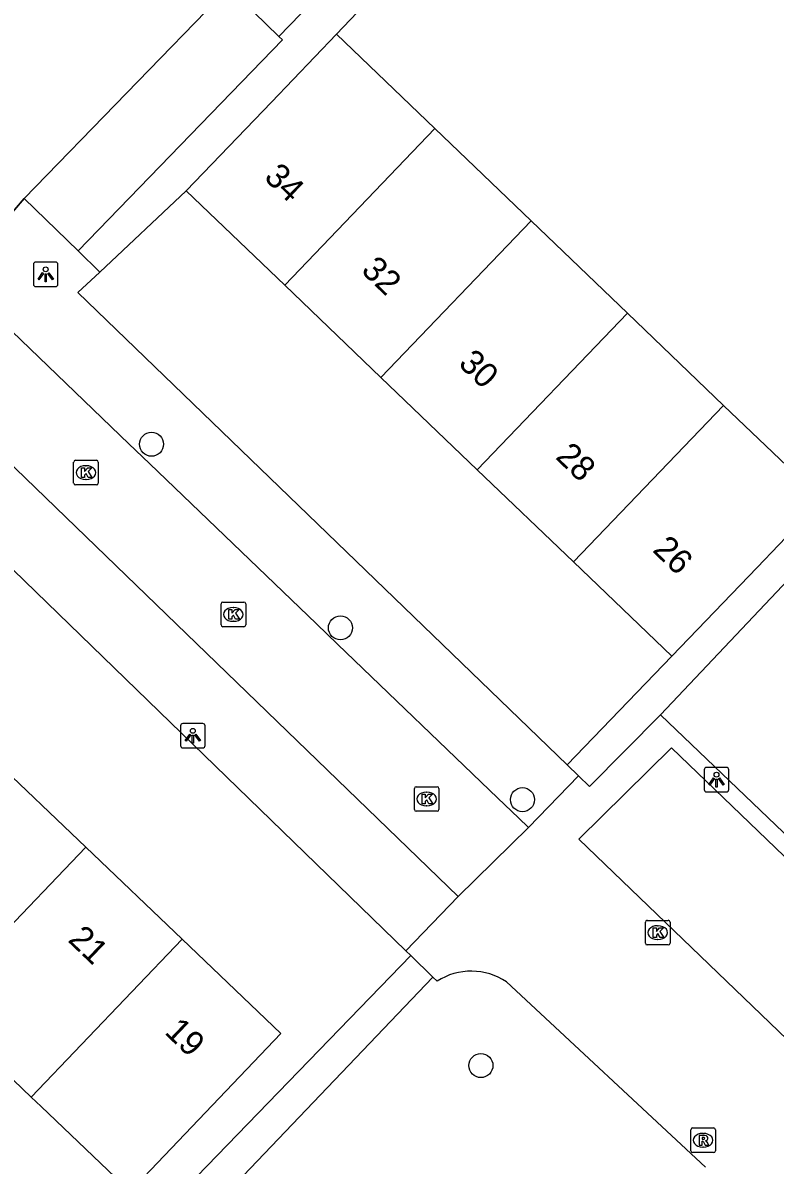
# Model space of a CAD drawing. Extents: x 158474 to 159560, y 388525 to 389605.
# Drawn here: x 159067.09 to 159097.68, y 388787.5 to 388833.95 of the extents above; entities that cross this region are included whole.
import ezdxf

# ---------------------------------------------------------------- set-up
doc = ezdxf.new("R2010")
doc.units = 0
for name, color, linetype in [('IMGEO_Boom', 7, 'Continuous'), ('IMGEO_Kolk', 7, 'Continuous'), ('IMGEO_Lichtpunt', 7, 'Continuous'), ('IMGEO_Muur', 7, 'Continuous'), ('IMGEO_Pand', 7, 'Continuous'), ('IMGEO_Pand_nummerreeks', 7, 'Continuous'), ('IMGEO_Rijbaan_lokaal_open', 7, 'Continuous'), ('IMGEO_Rioolput', 7, 'Continuous'), ('IMGEO_Voetpad_open', 7, 'Continuous')]:
    doc.layers.add(name, color=color, linetype=linetype)

msp = doc.modelspace()

# ---------------------------------------------------------------- linework, layer by layer
at = {"layer": 'IMGEO_Boom'}
for centre in [(159072.325, 388816.819), (159080.007, 388809.351), (159087.409, 388802.366), (159085.718, 388791.554)]:
    msp.add_circle(centre, 0.489, dxfattribs=at)
at = {"layer": 'IMGEO_Kolk'}
for p, q in [((159069.159, 388815.239), (159069.159, 388816.091)), ((159069.234, 388816.165), (159070.086, 388816.165)), ((159069.647, 388815.945), (159069.672, 388815.945)), ((159070.16, 388816.091), (159070.16, 388815.239)), ((159070.086, 388815.165), (159069.234, 388815.165)), ((159069.67, 388815.385), (159069.645, 388815.385)), ((159075.228, 388810.399), (159076.08, 388810.399)), ((159075.153, 388809.473), (159075.153, 388810.325)), ((159075.641, 388810.179), (159075.666, 388810.179)), ((159076.154, 388810.325), (159076.154, 388809.473)), ((159075.664, 388809.619), (159075.639, 388809.619)), ((159076.08, 388809.399), (159075.228, 388809.399)), ((159083.012, 388801.967), (159083.012, 388802.819)), ((159083.087, 388802.893), (159083.939, 388802.893)), ((159083.5, 388802.673), (159083.525, 388802.673)), ((159084.013, 388802.819), (159084.013, 388801.967)), ((159083.523, 388802.113), (159083.498, 388802.113)), ((159083.939, 388801.893), (159083.087, 388801.893)), ((159092.408, 388796.533), (159092.408, 388797.385)), ((159092.483, 388797.459), (159093.335, 388797.459)), ((159093.409, 388797.385), (159093.409, 388796.533)), ((159092.896, 388797.239), (159092.921, 388797.239)), ((159093.335, 388796.459), (159092.483, 388796.459)), ((159092.919, 388796.679), (159092.894, 388796.679))]:
    msp.add_line(p, q, dxfattribs=at)
for points in [[(159069.159, 388815.239), (159069.159, 388816.091)], [(159069.234, 388816.165), (159070.086, 388816.165)], [(159070.16, 388816.091), (159070.16, 388815.239)], [(159069.48, 388815.865), (159069.603, 388815.865), (159069.603, 388815.714), (159069.733, 388815.865), (159069.897, 388815.865), (159069.751, 388815.714), (159069.904, 388815.465), (159069.752, 388815.465), (159069.667, 388815.629), (159069.603, 388815.562), (159069.603, 388815.465), (159069.48, 388815.465), (159069.48, 388815.865)], [(159070.086, 388815.165), (159069.234, 388815.165)], [(159075.228, 388810.399), (159076.08, 388810.399)], [(159075.153, 388809.473), (159075.153, 388810.325)], [(159075.474, 388810.099), (159075.597, 388810.099), (159075.597, 388809.948), (159075.727, 388810.099), (159075.891, 388810.099), (159075.745, 388809.948), (159075.898, 388809.699), (159075.746, 388809.699), (159075.661, 388809.863), (159075.597, 388809.796), (159075.597, 388809.699), (159075.474, 388809.699), (159075.474, 388810.099)], [(159076.154, 388810.325), (159076.154, 388809.473)], [(159076.08, 388809.399), (159075.228, 388809.399)], [(159083.012, 388801.967), (159083.012, 388802.819)], [(159083.087, 388802.893), (159083.939, 388802.893)], [(159083.333, 388802.593), (159083.456, 388802.593), (159083.456, 388802.442), (159083.586, 388802.593), (159083.75, 388802.593), (159083.604, 388802.442), (159083.757, 388802.193), (159083.605, 388802.193), (159083.52, 388802.357), (159083.456, 388802.29), (159083.456, 388802.193), (159083.333, 388802.193), (159083.333, 388802.593)], [(159084.013, 388802.819), (159084.013, 388801.967)], [(159083.939, 388801.893), (159083.087, 388801.893)], [(159092.408, 388796.533), (159092.408, 388797.385)], [(159092.483, 388797.459), (159093.335, 388797.459)], [(159093.409, 388797.385), (159093.409, 388796.533)], [(159092.729, 388797.159), (159092.852, 388797.159), (159092.852, 388797.008), (159092.982, 388797.159), (159093.146, 388797.159), (159093, 388797.008), (159093.153, 388796.759), (159093.001, 388796.759), (159092.916, 388796.923), (159092.852, 388796.856), (159092.852, 388796.759), (159092.729, 388796.759), (159092.729, 388797.159)], [(159093.335, 388796.459), (159092.483, 388796.459)]]:
    msp.add_lwpolyline(points, dxfattribs=at)
for centre, start, end in [((159069.236, 388816.089), 91.552, 178.448), ((159069.236, 388816.089), 91.552, 178.448), ((159070.084, 388816.089), 1.552, 88.448), ((159070.084, 388816.089), 1.552, 88.448), ((159069.236, 388815.241), 181.552, 268.448), ((159069.236, 388815.241), 181.552, 268.448), ((159070.084, 388815.241), 271.552, 358.448), ((159070.084, 388815.241), 271.552, 358.448), ((159075.23, 388810.323), 91.552, 178.448), ((159075.23, 388810.323), 91.552, 178.448), ((159076.078, 388810.323), 1.552, 88.448), ((159076.078, 388810.323), 1.552, 88.448), ((159075.23, 388809.475), 181.552, 268.448), ((159075.23, 388809.475), 181.552, 268.448), ((159076.078, 388809.475), 271.552, 358.448), ((159076.078, 388809.475), 271.552, 358.448), ((159083.089, 388802.817), 91.552, 178.448), ((159083.089, 388802.817), 91.552, 178.448), ((159083.937, 388802.817), 1.552, 88.448), ((159083.937, 388802.817), 1.552, 88.448), ((159083.089, 388801.969), 181.552, 268.448), ((159083.089, 388801.969), 181.552, 268.448), ((159083.937, 388801.969), 271.552, 358.448), ((159083.937, 388801.969), 271.552, 358.448), ((159092.485, 388797.383), 91.552, 178.448), ((159092.485, 388797.383), 91.552, 178.448), ((159093.333, 388797.383), 1.552, 88.448), ((159093.333, 388797.383), 1.552, 88.448), ((159092.485, 388796.535), 181.552, 268.448), ((159092.485, 388796.535), 181.552, 268.448), ((159093.333, 388796.535), 271.552, 358.448), ((159093.333, 388796.535), 271.552, 358.448)]:
    msp.add_arc(centre, 0.0765, start, end, dxfattribs=at)
for centre, major_axis, ratio, start_param, end_param in [((159069.646, 388815.665), (-0.387, 0.002), 0.722429, 4.712389, 7.853982), ((159069.671, 388815.665), (-0.39, 0.002), 0.717154, 1.570796, 4.712389), ((159075.64, 388809.899), (-0.387, 0.002), 0.722429, 4.712389, 7.853982), ((159075.665, 388809.899), (-0.39, 0.002), 0.717154, 1.570796, 4.712389), ((159083.499, 388802.393), (-0.387, 0.002), 0.722429, 4.712389, 7.853982), ((159083.524, 388802.393), (-0.39, 0.002), 0.717154, 1.570796, 4.712389), ((159092.895, 388796.959), (-0.387, 0.002), 0.722429, 4.712389, 7.853982), ((159092.92, 388796.959), (-0.39, 0.002), 0.717154, 1.570796, 4.712389)]:
    msp.add_ellipse(centre, major_axis=major_axis, ratio=ratio, start_param=start_param, end_param=end_param, dxfattribs=at)
at = {"layer": 'IMGEO_Lichtpunt'}
for p, q in [((159067.523, 388824.132), (159067.523, 388823.325)), ((159067.523, 388824.132), (159067.523, 388823.325)), ((159068.425, 388824.227), (159067.617, 388824.227)), ((159068.425, 388824.227), (159067.617, 388824.227)), ((159068.519, 388823.325), (159068.519, 388824.132)), ((159068.519, 388823.325), (159068.519, 388824.132)), ((159067.617, 388823.231), (159068.425, 388823.231)), ((159067.617, 388823.231), (159068.425, 388823.231)), ((159073.505, 388805.369), (159073.505, 388804.562)), ((159073.505, 388805.369), (159073.505, 388804.562)), ((159074.407, 388805.464), (159073.599, 388805.464)), ((159074.407, 388805.464), (159073.599, 388805.464)), ((159074.501, 388804.562), (159074.501, 388805.369)), ((159074.501, 388804.562), (159074.501, 388805.369)), ((159073.599, 388804.468), (159074.407, 388804.468)), ((159073.599, 388804.468), (159074.407, 388804.468)), ((159094.797, 388803.585), (159094.797, 388802.778)), ((159094.797, 388803.585), (159094.797, 388802.778)), ((159095.699, 388803.68), (159094.891, 388803.68)), ((159095.699, 388803.68), (159094.891, 388803.68)), ((159095.793, 388802.778), (159095.793, 388803.585)), ((159095.793, 388802.778), (159095.793, 388803.585)), ((159094.891, 388802.684), (159095.699, 388802.684)), ((159094.891, 388802.684), (159095.699, 388802.684))]:
    msp.add_line(p, q, dxfattribs=at)
for points in [[(159067.897, 388823.796), (159067.936, 388823.768), (159067.748, 388823.506), (159067.71, 388823.533), (159067.897, 388823.796)], [(159067.999, 388823.748), (159068.046, 388823.748), (159068.046, 388823.426), (159067.999, 388823.426), (159067.999, 388823.748)], [(159068.109, 388823.768), (159068.147, 388823.795), (159068.334, 388823.533), (159068.295, 388823.505), (159068.109, 388823.768)], [(159073.879, 388805.033), (159073.918, 388805.005), (159073.73, 388804.743), (159073.692, 388804.77), (159073.879, 388805.033)], [(159073.981, 388804.985), (159074.028, 388804.985), (159074.028, 388804.663), (159073.981, 388804.663), (159073.981, 388804.985)], [(159074.091, 388805.005), (159074.129, 388805.032), (159074.316, 388804.77), (159074.277, 388804.742), (159074.091, 388805.005)], [(159095.171, 388803.249), (159095.21, 388803.221), (159095.022, 388802.959), (159094.984, 388802.986), (159095.171, 388803.249)], [(159095.273, 388803.201), (159095.32, 388803.201), (159095.32, 388802.879), (159095.273, 388802.879), (159095.273, 388803.201)], [(159095.383, 388803.221), (159095.421, 388803.248), (159095.608, 388802.986), (159095.569, 388802.958), (159095.383, 388803.221)]]:
    msp.add_lwpolyline(points, dxfattribs=at)
for centre in [(159068.022, 388823.93), (159074.004, 388805.167), (159095.296, 388803.383)]:
    msp.add_circle(centre, 0.0994, dxfattribs=at)
for centre, start, end in [((159067.617, 388824.132), 90, 180), ((159067.617, 388824.132), 90, 180), ((159068.425, 388824.132), 0, 90), ((159068.425, 388824.132), 0, 90), ((159067.617, 388823.325), 180, 270), ((159067.617, 388823.325), 180, 270), ((159068.425, 388823.325), 270, 0), ((159068.425, 388823.325), 270, 360), ((159073.599, 388805.369), 90, 180), ((159073.599, 388805.369), 90, 180), ((159074.407, 388805.369), 0, 90), ((159074.407, 388805.369), 0, 90), ((159073.599, 388804.562), 180, 270), ((159073.599, 388804.562), 180, 270), ((159074.407, 388804.562), 270, 0), ((159074.407, 388804.562), 270, 360), ((159094.891, 388803.585), 90, 180), ((159094.891, 388803.585), 90, 180), ((159095.699, 388803.585), 0, 90), ((159095.699, 388803.585), 0, 90), ((159094.891, 388802.778), 180, 270), ((159094.891, 388802.778), 180, 270), ((159095.699, 388802.778), 270, 0), ((159095.699, 388802.778), 270, 360)]:
    msp.add_arc(centre, 0.0946, start, end, dxfattribs=at)
at = {"layer": 'IMGEO_Muur'}
msp.add_lwpolyline([(159060.03, 388831.899), (159066.36, 388825.887), (159067.15, 388826.811)], dxfattribs=at)
at = {"layer": 'IMGEO_Pand'}
for points in [[(159077.507, 388833.404), (159075.462, 388835.387), (159067.15, 388826.811)], [(159077.507, 388833.404), (159077.651, 388833.265), (159069.34, 388824.689)], [(159073.738, 388827.125), (159077.199, 388830.735), (159079.843, 388833.493)], [(159079.843, 388833.493), (159083.846, 388829.656)], [(159083.846, 388829.656), (159077.74, 388823.288)], [(159083.846, 388829.656), (159087.76, 388825.904)], [(159077.74, 388823.288), (159073.738, 388827.125)], [(159067.15, 388826.811), (159069.34, 388824.689)], [(159081.655, 388819.536), (159087.76, 388825.904)], [(159087.76, 388825.904), (159091.675, 388822.152)], [(159081.655, 388819.536), (159077.74, 388823.288)], [(159085.57, 388815.784), (159091.675, 388822.152)], [(159091.675, 388822.152), (159095.589, 388818.4)], [(159085.57, 388815.784), (159081.655, 388819.536)], [(159095.589, 388818.4), (159089.484, 388812.031)], [(159095.589, 388818.4), (159099.59, 388814.565)], [(159089.484, 388812.031), (159085.57, 388815.784)], [(159099.59, 388814.565), (159096.945, 388811.806), (159093.485, 388808.196)], [(159093.485, 388808.196), (159089.484, 388812.031)], [(159065.757, 388804.152), (159069.655, 388800.43)], [(159062.133, 388792.577), (159069.655, 388800.43)], [(159069.655, 388800.43), (159073.568, 388796.694)], [(159073.568, 388796.694), (159077.589, 388792.855), (159071.457, 388786.433), (159067.841, 388789.886), (159067.438, 388790.271)], [(159067.438, 388790.271), (159073.568, 388796.694)], [(159067.438, 388790.271), (159065.261, 388792.349), (159063.881, 388790.909), (159062.133, 388792.577)]]:
    msp.add_lwpolyline(points, dxfattribs=at)
at = {"layer": 'IMGEO_Rijbaan_lokaal_open'}
for points in [[(159087.648, 388801.234), (159087.242, 388801.624), (159086.411, 388802.422), (159079.885, 388808.688), (159079.028, 388809.511), (159072.24, 388816.029), (159071.406, 388816.83), (159064.812, 388823.162)], [(159084.792, 388798.423), (159063.089, 388819.397), (159061.719, 388817.967)], [(159087.648, 388801.234), (159084.792, 388798.423)]]:
    msp.add_lwpolyline(points, dxfattribs=at)
at = {"layer": 'IMGEO_Rioolput'}
for p, q in [((159094.327, 388789.016), (159095.179, 388789.016)), ((159094.252, 388788.09), (159094.252, 388788.942)), ((159094.74, 388788.796), (159094.765, 388788.796)), ((159095.253, 388788.942), (159095.253, 388788.09)), ((159094.763, 388788.236), (159094.738, 388788.236)), ((159095.179, 388788.016), (159094.327, 388788.016))]:
    msp.add_line(p, q, dxfattribs=at)
for points in [[(159094.327, 388789.016), (159095.179, 388789.016)], [(159094.252, 388788.09), (159094.252, 388788.942)], [(159094.841, 388788.714), (159094.589, 388788.716), (159094.589, 388788.316)], [(159094.767, 388788.635), (159094.713, 388788.635), (159094.713, 388788.554)], [(159094.713, 388788.554), (159094.765, 388788.554)], [(159095.253, 388788.942), (159095.253, 388788.09)], [(159094.589, 388788.316), (159094.713, 388788.316), (159094.713, 388788.478), (159094.724, 388788.478)], [(159094.771, 388788.449), (159094.842, 388788.316), (159094.982, 388788.316), (159094.917, 388788.442)], [(159095.179, 388788.016), (159094.327, 388788.016)]]:
    msp.add_lwpolyline(points, dxfattribs=at)
for centre, radius, start, end in [((159094.329, 388788.94), 0.0765, 91.552, 178.448), ((159094.329, 388788.94), 0.0765, 91.552, 178.448), ((159095.177, 388788.94), 0.0765, 1.552, 88.448), ((159095.177, 388788.94), 0.0765, 1.552, 88.448), ((159094.749, 388788.743), 0.19, 274.7715, 282.9687), ((159094.773, 388788.539), 0.0964, 77.0061, 93.1865), ((159094.787, 388788.596), 0.0378, 276.6634, 79.6772), ((159094.84, 388788.604), 0.109, 350.3612, 89.416), ((159094.838, 388788.604), 0.112, 277.5842, 350.9817), ((159094.329, 388788.092), 0.0765, 181.552, 268.448), ((159094.329, 388788.092), 0.0765, 181.552, 268.448), ((159094.723, 388788.425), 0.0533, 26.0293, 88.6989), ((159094.822, 388788.389), 0.108, 29.5134, 73.7905), ((159095.177, 388788.092), 0.0765, 271.552, 358.448), ((159095.177, 388788.092), 0.0765, 271.552, 358.448)]:
    msp.add_arc(centre, radius, start, end, dxfattribs=at)
for centre, major_axis, ratio, start_param, end_param in [((159094.739, 388788.516), (-0.387, 0.002), 0.722429, 4.712389, 7.853982), ((159094.764, 388788.516), (-0.39, 0.002), 0.717154, 1.570796, 4.712389)]:
    msp.add_ellipse(centre, major_axis=major_axis, ratio=ratio, start_param=start_param, end_param=end_param, dxfattribs=at)
at = {"layer": 'IMGEO_Voetpad_open'}
for points in [[(159104.695, 388858.002), (159093.153, 388848.171), (159092.503, 388848.873), (159077.507, 388833.404)], [(159090.402, 388844.391), (159090.316, 388844.473), (159079.843, 388833.493)], [(159067.15, 388826.811), (159066.36, 388825.887), (159060.03, 388831.899), (159053.839, 388837.78)], [(159070.217, 388823.817), (159073.738, 388827.125)], [(159093.025, 388805.817), (159113.083, 388827.03), (159122.795, 388817.848), (159124.297, 388813.463)], [(159069.34, 388824.689), (159070.217, 388823.817)], [(159070.217, 388823.817), (159069.331, 388822.993), (159089.222, 388803.782)], [(159058.591, 388812.47), (159062.134, 388816.124), (159082.662, 388796.225)], [(159093.485, 388808.196), (159089.222, 388803.782)], [(159089.681, 388803.339), (159090.139, 388802.896), (159093.025, 388805.817)], [(159105.196, 388794.173), (159093.025, 388805.817)], [(159100.291, 388790.584), (159089.696, 388800.758), (159093.465, 388804.467), (159104.059, 388794.294), (159100.291, 388790.584)], [(159089.222, 388803.782), (159089.681, 388803.339)], [(159089.681, 388803.339), (159087.648, 388801.234)], [(159082.662, 388796.225), (159084.792, 388798.423)], [(159062.115, 388778.729), (159064.202, 388776.767), (159082.869, 388796.024)], [(159082.662, 388796.225), (159082.869, 388796.024)], [(159082.869, 388796.024), (159083.769, 388795.152)], [(159071.478, 388782.279), (159083.769, 388795.152)], [(159083.769, 388795.152), (159083.94, 388794.986)], [(159086.755, 388794.96), (159094.845, 388787.419)]]:
    msp.add_lwpolyline(points, dxfattribs=at)
msp.add_arc((159085.328, 388792.818), 2.574, 56.3155, 122.6261, dxfattribs=at)

# ---------------------------------------------------------------- texts
at = {"layer": 'IMGEO_Pand_nummerreeks'}
for s, rotation, p in [('34', 316.2116, (159076.86, 388827.623)), ('32', 316.2116, (159080.808, 388823.839)), ('30', 316.2116, (159084.761, 388820.049)), ('28', 316.2116, (159088.711, 388816.263)), ('26', 316.2116, (159092.658, 388812.479)), ('21', 316.3249, (159068.888, 388796.627)), ('19', 316.3249, (159072.819, 388792.874))]:
    msp.add_text(s, height=1, rotation=rotation, dxfattribs=at).set_placement(p)

doc.saveas('drawing.dxf')
